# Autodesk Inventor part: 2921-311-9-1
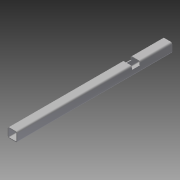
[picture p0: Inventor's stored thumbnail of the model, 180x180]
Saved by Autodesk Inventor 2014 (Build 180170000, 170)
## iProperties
Company: NHTSA/VRTC
Created: 2012-02
Part Number: 2921-311-9-1
Project: CHILD SIDE IMPACT sLED
Material: Steel, Mild
Description: T.S. 1 1/2" x 1 1/2" x 1/8" x 623.8 mm (24.56")
Document SubType Name: Modeling
Designer: Dave Walker
Mass: 2000.37 g
Surface Area: 1617.22 cm^2
Volume: 254.5 cm^3
Density: 7.86 g/cm^3
Appearance: Steel
Title: BENCH FRAME TUBE #8
Subject: Child Side Impact Sled
Author: Dave Walker
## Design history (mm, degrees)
sketch "Sketch1"
  geometry: L1 (12.7, -19.05)-(-12.7, -19.05); L2 (-19.05, -12.7)-(-19.05, 12.7); L3 (-12.7, 19.05)-(12.7, 19.05); L4 (19.05, 12.7)-(19.05, -12.7); L5 (0, 28.511)-(0, -28.511) reference; L6 (-28.511, 0)-(28.511, 0) reference; L7 (12.7, 15.875)-(-12.7, 15.875); L8 (-15.875, 12.7)-(-15.875, -12.7); L9 (-12.7, -15.875)-(12.7, -15.875); L10 (15.875, -12.7)-(15.875, 12.7); A1 r 6.35 centre (-12.7, -12.7) between (-19.05, -12.7) and (-12.7, -19.05); A2 r 6.35 centre (-12.7, 12.7) between (-12.7, 19.05) and (-19.05, 12.7); A3 r 6.35 centre (12.7, 12.7) between (19.05, 12.7) and (12.7, 19.05); A4 r 6.35 centre (12.7, -12.7) between (12.7, -19.05) and (19.05, -12.7); A5 r 3.175 centre (-12.7, 12.7) between (-12.7, 15.875) and (-15.875, 12.7); A6 r 3.175 centre (-12.7, -12.7) between (-15.875, -12.7) and (-12.7, -15.875); A7 r 3.175 centre (12.7, -12.7) between (12.7, -15.875) and (15.875, -12.7); A8 r 3.175 centre (12.7, 12.7) between (15.875, 12.7) and (12.7, 15.875); 3 further points
  constraints: 16 end point, 16 point on circle, 8 centre point, 8 tangent, 6 point on line, 4 parallel, 3 equal radius, 2 perpendicular, 1 horizontal, 9 other
  dimensions: "d0" = 38.1 distance of point (-19.05, -19.05) point (-19.05, 19.05); "d1" = 38.1 distance of point (19.05, -19.05) point (-19.05, -19.05); "d2" = 6.35 radius of A1; "d3" = 3.175 distance between parallel lines of L3 L7
extrude "Extrusion1" new body sketch "Sketch1" distance "d4" = 623.8; taper "d5" = 0 deg
sketch "Sketch3"
  geometry: L1 (461.3, 31.75)-(494.6, 31.75); L2 (494.6, 31.75)-(494.6, 17.25); L3 (494.6, 17.25)-(461.3, 17.25); L4 (461.3, 17.25)-(461.3, 31.75); L5 (0, 31.75)-(623.8, 31.75) reference; L6 (623.8, 31.75)-(623.8, 25.4) reference; 1 further point
  constraints: 8 end point, 2 parallel, 1 collinear, 1 horizontal, 1 perpendicular
  dimensions: "d10" = 129.2 distance between parallel lines of L2 L6; "d11" = 33.3 distance between parallel lines of L4 L2; "d12" = 14.5 distance between parallel lines of L3 L5
extrude "Extrusion3" cut sketch "Sketch3" stored distance "d13" = 10; taper "d14" = 0 deg
body "Solid1"
